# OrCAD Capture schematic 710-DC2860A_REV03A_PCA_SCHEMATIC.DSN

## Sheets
1 PAGE1: size Custom; company: ANALOG DEVICES; note: DEMO BOARD BILL OF MATERIALS; note: 40V,1.2A QUAD STEP-DOWN SILENT SWITCHER uMODULE REGULATOR
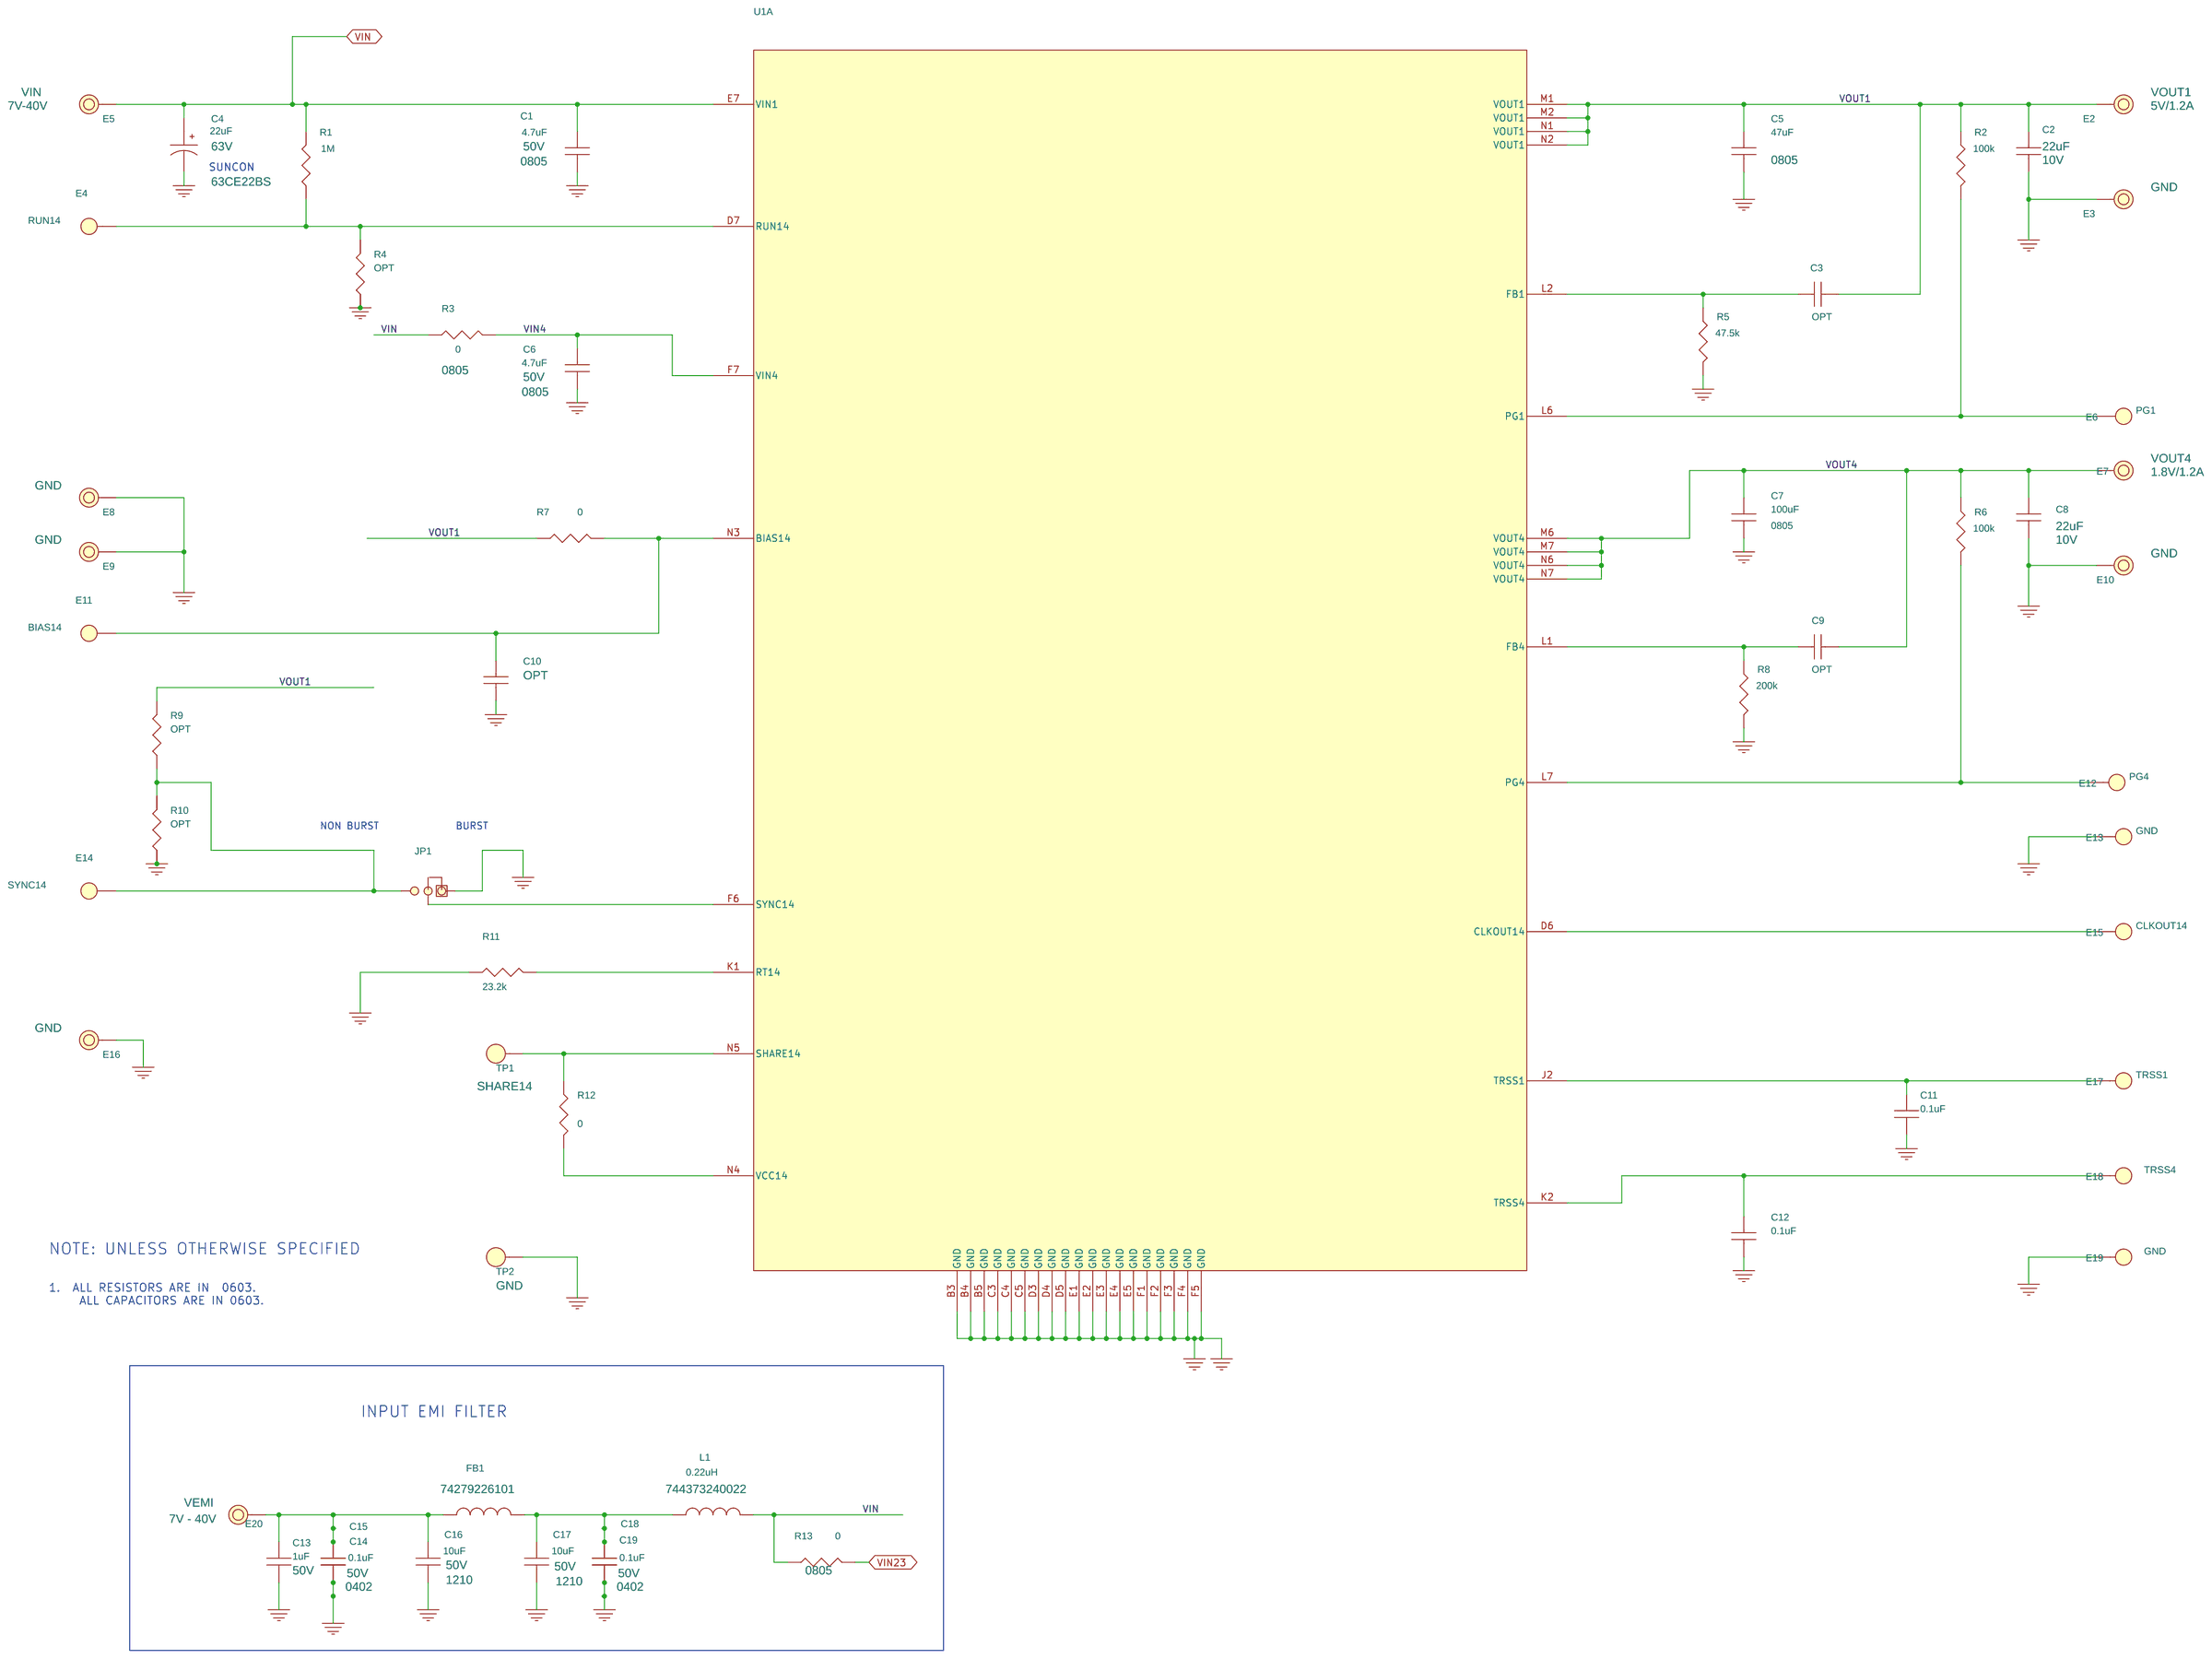
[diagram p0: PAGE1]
2 PAGE2: size Custom
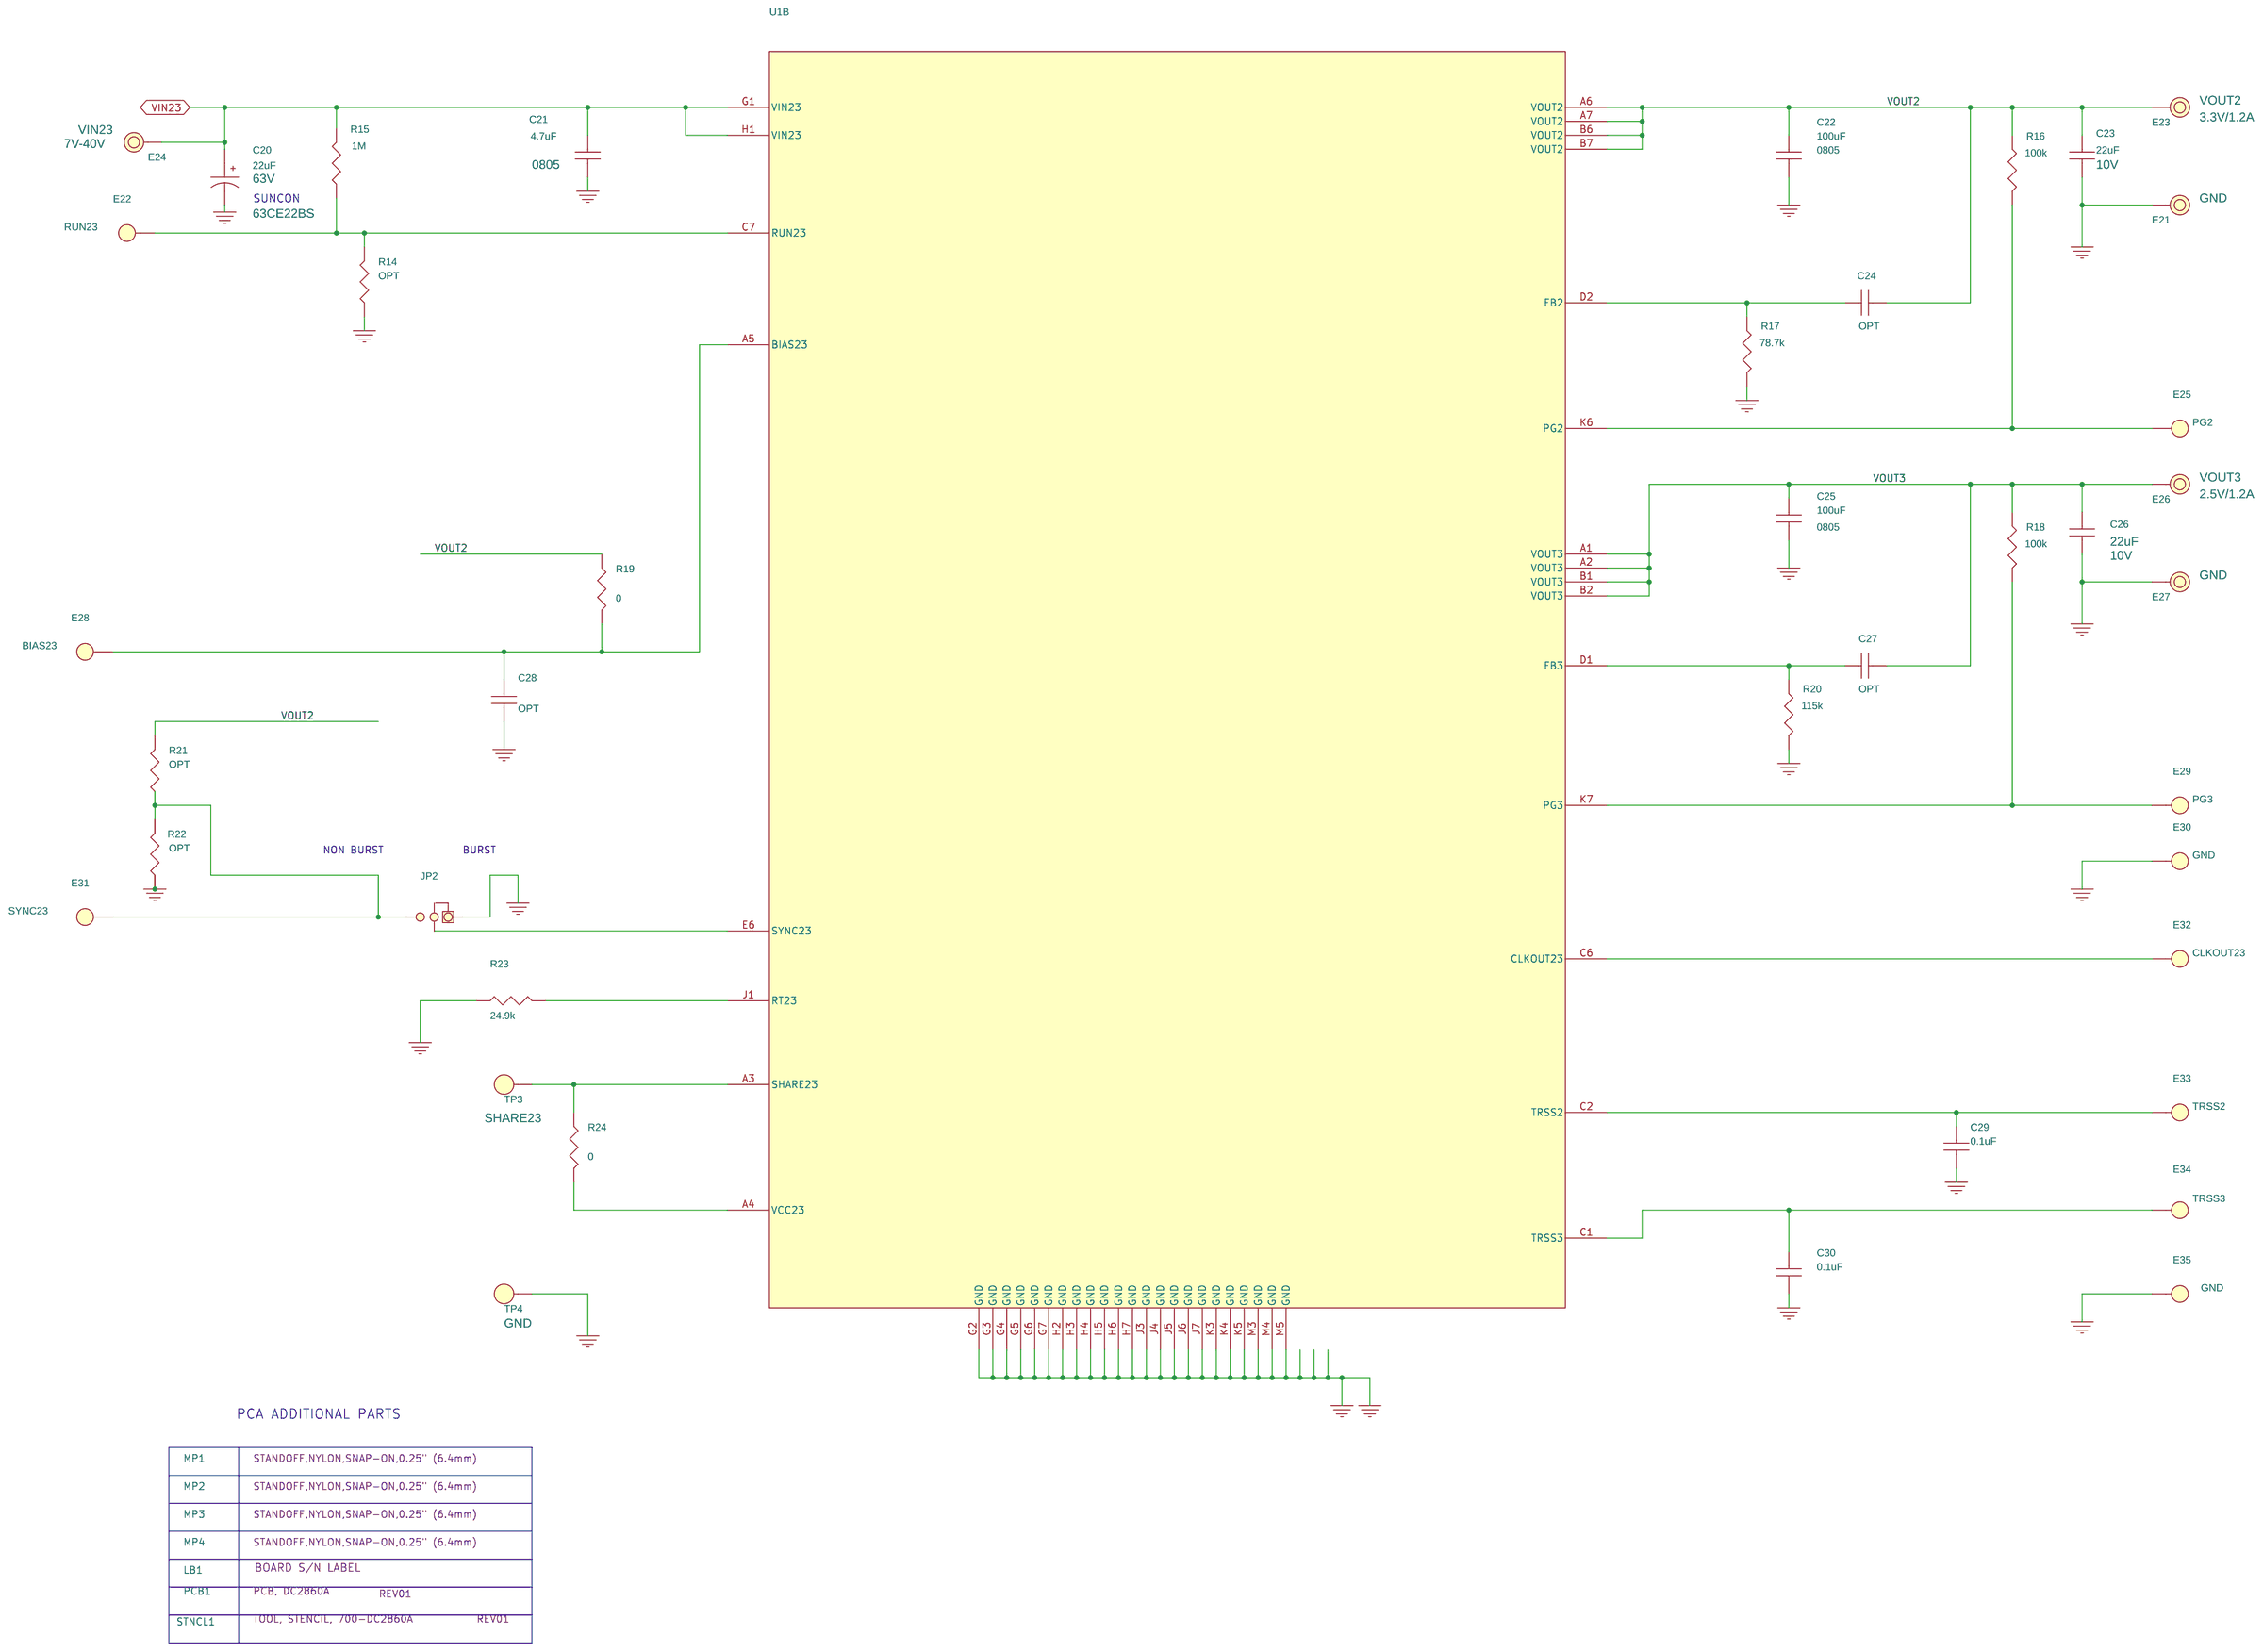
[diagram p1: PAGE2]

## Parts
sheet PAGE1
C1  4.7uF  [CC0805N]
C2  22uF  [CC0603N]
C3  OPT  [CC0603N]
C4  22uF  [SUNCON_CE-BS_6.3X7.7]
C5  47uF  [CC0805N]
C6  4.7uF  [CC0805N]
C7  100uF  [CC0805N]
C8  22uF  [CC0603N]
C9  OPT  [CC0603N]
C10  OPT  [CC0603N]
C11  0.1uF  [CC0603N]
C12  0.1uF  [CC0603N]
C13  1uF  [CC0603N]
C14  0.1uF  [CC0402N]
C15  0.1uF  [CC0402N]
C16  10uF  [CC1210N]
C17  10uF  [CC1210N]
C18  0.1uF  [CC0402N]
C19  0.1uF  [CC0402N]
E2  TEST POINT  [MILLMAX2501]
E3  TEST POINT  [MILLMAX2501]
E4  TEST POINT  [MILLMAX2308]
E5  TEST POINT  [MILLMAX2501]
E6  TEST POINT  [MILLMAX2308]
E7  TEST POINT  [MILLMAX2501]
E8  TEST POINT  [MILLMAX2501]
E9  TEST POINT  [MILLMAX2501]
E10  TEST POINT  [MILLMAX2501]
E11  TEST POINT  [MILLMAX2308]
E12  TEST POINT  [MILLMAX2308]
E13  TEST POINT  [MILLMAX2308]
E14  TEST POINT  [MILLMAX2308]
E15  TEST POINT  [MILLMAX2308]
E16  TEST POINT  [MILLMAX2501]
E17  TEST POINT  [MILLMAX2308]
E18  TEST POINT  [MILLMAX2308]
E19  TEST POINT  [MILLMAX2308]
E20  TEST POINT  [MILLMAX2501]
FB1  100 OHMS@100MHz  [WURTH-74279226101]
JP1  HDR.  [HD1X3-079]
L1  0.22uH  [WURTH-744373240022]
R1  1M  [CR0603N]
R2  100k  [CR0603N]
R3  0  [CR0805N]
R4  OPT  [CR0603N]
R5  47.5k  [CR0603N]
R6  100k  [CR0603N]
R7  0  [CR0603N]
R8  200k  [CR0603N]
R9  OPT  [CR0603N]
R10  OPT  [CR0603N]
R11  23.2k  [CR0603N]
R12  0  [CR0603N]
R13  0  [CR0805N]
TP1  SHARE14  [TEST-PIN]
TP2  GND  [TEST-PIN]
XJP1  SHUNT
sheet PAGE2
C20  22uF  [SUNCON_CE-BS_6.3X7.7]
C21  4.7uF  [CC0805N]
C22  100uF  [CC0805N]
C23  22uF  [CC0603N]
C24  OPT  [CC0603N]
C25  100uF  [CC0805N]
C26  22uF  [CC0603N]
C27  OPT  [CC0603N]
C28  OPT  [CC0603N]
C29  0.1uF  [CC0603N]
C30  0.1uF  [CC0603N]
E21  TEST POINT  [MILLMAX2501]
E22  TEST POINT  [MILLMAX2308]
E23  TEST POINT  [MILLMAX2501]
E24  TEST POINT  [MILLMAX2501]
E25  TEST POINT  [MILLMAX2308]
E26  TEST POINT  [MILLMAX2501]
E27  TEST POINT  [MILLMAX2501]
E28  TEST POINT  [MILLMAX2308]
E29  TEST POINT  [MILLMAX2308]
E30  TEST POINT  [MILLMAX2308]
E31  TEST POINT  [MILLMAX2308]
E32  TEST POINT  [MILLMAX2308]
E33  TEST POINT  [MILLMAX2308]
E34  TEST POINT  [MILLMAX2308]
E35  TEST POINT  [MILLMAX2308]
JP2  HDR.  [HD1X3-079]
LB1  LABEL  [895-0154_REV01]
MP1  STANDOFF  [MTG-8831]
MP2  STANDOFF  [MTG-8831]
MP3  STANDOFF  [MTG-8831]
MP4  STANDOFF  [MTG-8831]
PCB1  PCB, DC2860A
R14  OPT  [CR0603N]
R15  1M  [CR0603N]
R16  100k  [CR0603N]
R17  78.7k  [CR0603N]
R18  100k  [CR0603N]
R19  0  [CR0603N]
R20  115k  [CR0603N]
R21  OPT  [CR0603N]
R22  OPT  [CR0603N]
R23  24.9k  [CR0603N]
R24  0  [CR0603N]
STNCL1  TOOL, STENCIL, 700-DC2860A
TP3  SHARE23  [TEST-PIN]
TP4  GND  [TEST-PIN]
U1  LTM8051-BGA  [LTC-BGA-91-1608]  (sections A,B)
XJP2  SHUNT

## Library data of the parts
C1 C6 = CAP: CAP.,4.7uF,X5R,50V,10%,0805; CLASS: DISCRETE; Dielectric Type: X5R; FPLIST: CC0805N,CC0805L,CC0805M; Inventory Qty: 8500; Manufacturer: MURATA; Manufacturer PN: GRM21BR61H475KE51L; PART_NUMBER: 150-0172; Package Size: 0805; Rated Voltage: 50V; Tolerance: 10%
C2 C8 = CAP: CAP.,22uF,X5R,10V,20%,0603; CLASS: DISCRETE; Dielectric Type: X5R; FPLIST: CC0603N,CC0603L,CC0603M; Inventory Qty: 17834; Manufacturer: AVX; Manufacturer PN: 0603ZD226MAT2A; PART_NUMBER: 150-2341; Package Size: 0603; Package Type: Surface Mount, MLCC; Rated Voltage: 10V; Temperature Coefficient: X5R; Tolerance: 20%
C3 C9 C10 = CAP: CAP., OPTION, 0603; CLASS: DISCRETE; FPLIST: CC0603N,CC0603L,CC0603M; PART_NUMBER: 150-3038; Package Size: 0603; Package Type: SMD
C4 C20 = CAP_P_ALT: CAP.,22uF,ALUM. ELECT.,63V,20%,6.3x7.7mm,CE-BS; CLASS: DISCRETE; Dielectric Type: ALUM. ELECT.; Inventory Qty: 8902; Manufacturer: SUN ELECTRONIC INDUSTRIES CORP; Manufacturer PN: 63CE22BS; PART_NUMBER: 150-3334; Package Size: 6.3x7.7mm; Rated Voltage: 63V; Tolerance: 20%
C5 = CAP: CAP.,47uF,X5R,6.3V,20%,0805; CLASS: DISCRETE; Dielectric Type: X5R; FPLIST: CC0805N,CC0805L,CC0805M; Inventory Qty: 29976; Manufacturer: MURATA; Manufacturer PN: GRM21BR60J476ME15L; PART_NUMBER: 150-0140; Package Size: 0805; Rated Voltage: 6.3V; Tolerance: 20%
C7 = CAP: CAP.,100uF,X5R,6.3V,20%,0805; CLASS: DISCRETE; Dielectric Type: X5R; FPLIST: CC0805N,CC0805L,CC0805M; Inventory Qty: 2920; Manufacturer: MURATA; Manufacturer PN: GRM21BR60J107ME15K; PART_NUMBER: 150-0728; Package Size: 0805; Package Type: Surface Mount, MLCC; Rated Voltage: 6.3V; Temperature Coefficient: X5R; Tolerance: 20%
C11 C12 = CAP: CAP.,0.1uF,X5R,16V,10%,0603; CLASS: DISCRETE; Dielectric Type: X5R; FPLIST: CC0603N,CC0603L,CC0603M; Inventory Qty: 21908; Manufacturer: AVX; Manufacturer PN: 0603YD104KAT2A; PART_NUMBER: 150-3328; Package Size: 0603; Rated Voltage: 16V; Tolerance: 10%
C13 = CAP: CAP.,1uF,X5R,50V,10%,0603; CLASS: DISCRETE; Dielectric Type: X5R; FPLIST: CC0603N,CC0603L,CC0603M; Inventory Qty: 11686; Manufacturer: AVX; Manufacturer PN: 06035D105KAT2A; PART_NUMBER: 150-3292; Package Size: 0603; Package Type: SMD; Rated Voltage: 50V; Tolerance: 10%
C14 C15 C18 C19 = CAP: CAP.,0.1uF,X7R,50V,10%,0402; CLASS: DISCRETE; Dielectric Type: X7R; FPLIST: CC0402N,CC0402L,CC0402M; Inventory Qty: 320056; Manufacturer: AVX; Manufacturer PN: 04025C104KAT2A; PART_NUMBER: 150-3240; Package Size: 0402; Package Type: SMD; Rated Voltage: 50V; Tolerance: 10%
C16 C17 = CAP: CAP.,10uF,X5R,50V,10%,1210; CLASS: DISCRETE; Dielectric Type: X5R; FPLIST: CC1210N,CC1210L,CC1210M; Inventory Qty: 11106; Manufacturer: TDK; Manufacturer PN: C3225X5R1H106K250AB; PART_NUMBER: 150-3288; Package Size: 1210; Rated Voltage: 50V; Tolerance: 10%
E2 = TESTPOINT_.219_MILL-MAX_2501: TEST POINT,TURRET,0.094" MTG. HOLE,PCB 0.062" THK; CLASS: IO; Inventory Qty: 444100; Manufacturer: MILL-MAX; Manufacturer PN: 2501-2-00-80-00-00-07-0; PART_FIELD_01: VOUT1; PART_FIELD_02: 5V/1.2A; PART_NUMBER: 260-0003
E3 E8 E21 E27 = TESTPOINT_.219_MILL-MAX_2501: TEST POINT,TURRET,0.094" MTG. HOLE,PCB 0.062" THK; CLASS: IO; Inventory Qty: 444100; Manufacturer: MILL-MAX; Manufacturer PN: 2501-2-00-80-00-00-07-0; PART_FIELD_01: GND; PART_NUMBER: 260-0003
E4 = TEST_POINT_.156_MILL-MAX_2308: TEST POINT,TURRET,0.064" MTG. HOLE,PCB 0.062" THK; CLASS: IO; Inventory Qty: 751543; Manufacturer: MILL-MAX; Manufacturer PN: 2308-2-00-80-00-00-07-0; PART_FIELD_01: RUN14; PART_NUMBER: 260-0004
E5 = TESTPOINT_.219_MILL-MAX_2501: TEST POINT,TURRET,0.094" MTG. HOLE,PCB 0.062" THK; CLASS: IO; Inventory Qty: 444100; Manufacturer: MILL-MAX; Manufacturer PN: 2501-2-00-80-00-00-07-0; PART_FIELD_01: VIN; PART_FIELD_02: 7V-40V; PART_NUMBER: 260-0003
E6 = TEST_POINT_.156_MILL-MAX_2308: TEST POINT,TURRET,0.064" MTG. HOLE,PCB 0.062" THK; CLASS: IO; Inventory Qty: 751543; Manufacturer: MILL-MAX; Manufacturer PN: 2308-2-00-80-00-00-07-0; PART_FIELD_01: PG1; PART_NUMBER: 260-0004
E7 = TESTPOINT_.219_MILL-MAX_2501: TEST POINT,TURRET,0.094" MTG. HOLE,PCB 0.062" THK; CLASS: IO; Inventory Qty: 444100; Manufacturer: MILL-MAX; Manufacturer PN: 2501-2-00-80-00-00-07-0; PART_FIELD_01: VOUT4; PART_FIELD_02: 1.8V/1.2A; PART_NUMBER: 260-0003
E9 E10 E16 = TESTPOINT_.219_MILL-MAX_2501: TEST POINT,TURRET,0.094" MTG. HOLE,PCB 0.062" THK; CLASS: IO; Inventory Qty: 444100; Manufacturer: MILL-MAX; Manufacturer PN: 2501-2-00-80-00-00-07-0; PART_FIELD_01: GND; PART_FIELD_02: <PART_FIELD_02>; PART_NUMBER: 260-0003
E11 = TEST_POINT_.156_MILL-MAX_2308: TEST POINT,TURRET,0.064" MTG. HOLE,PCB 0.062" THK; CLASS: IO; Inventory Qty: 751543; Manufacturer: MILL-MAX; Manufacturer PN: 2308-2-00-80-00-00-07-0; PART_FIELD_01: BIAS14; PART_NUMBER: 260-0004
E12 = TEST_POINT_.156_MILL-MAX_2308: TEST POINT,TURRET,0.064" MTG. HOLE,PCB 0.062" THK; CLASS: IO; Inventory Qty: 751543; Manufacturer: MILL-MAX; Manufacturer PN: 2308-2-00-80-00-00-07-0; PART_FIELD_01: PG4; PART_NUMBER: 260-0004
E13 E19 E30 E35 = TEST_POINT_.156_MILL-MAX_2308: TEST POINT,TURRET,0.064" MTG. HOLE,PCB 0.062" THK; CLASS: IO; Inventory Qty: 751543; Manufacturer: MILL-MAX; Manufacturer PN: 2308-2-00-80-00-00-07-0; PART_FIELD_01: GND; PART_NUMBER: 260-0004
E14 = TEST_POINT_.156_MILL-MAX_2308: TEST POINT,TURRET,0.064" MTG. HOLE,PCB 0.062" THK; CLASS: IO; Inventory Qty: 751543; Manufacturer: MILL-MAX; Manufacturer PN: 2308-2-00-80-00-00-07-0; PART_FIELD_01: SYNC14; PART_NUMBER: 260-0004
E15 = TEST_POINT_.156_MILL-MAX_2308: TEST POINT,TURRET,0.064" MTG. HOLE,PCB 0.062" THK; CLASS: IO; Inventory Qty: 751543; Manufacturer: MILL-MAX; Manufacturer PN: 2308-2-00-80-00-00-07-0; PART_FIELD_01: CLKOUT14; PART_NUMBER: 260-0004
E17 = TEST_POINT_.156_MILL-MAX_2308: TEST POINT,TURRET,0.064" MTG. HOLE,PCB 0.062" THK; CLASS: IO; Inventory Qty: 751543; Manufacturer: MILL-MAX; Manufacturer PN: 2308-2-00-80-00-00-07-0; PART_FIELD_01: TRSS1; PART_NUMBER: 260-0004
E18 = TEST_POINT_.156_MILL-MAX_2308: TEST POINT,TURRET,0.064" MTG. HOLE,PCB 0.062" THK; CLASS: IO; Inventory Qty: 751543; Manufacturer: MILL-MAX; Manufacturer PN: 2308-2-00-80-00-00-07-0; PART_FIELD_01: TRSS4; PART_NUMBER: 260-0004
E20 = TESTPOINT_.219_MILL-MAX_2501: TEST POINT,TURRET,0.094" MTG. HOLE,PCB 0.062" THK; CLASS: IO; Inventory Qty: 444100; Manufacturer: MILL-MAX; Manufacturer PN: 2501-2-00-80-00-00-07-0; PART_FIELD_01: VEMI; PART_FIELD_02: 7V - 40V; PART_NUMBER: 260-0003
FB1 = IND_ALT: IND.,100 OHMS@100MHz,FERRITE BEAD,25%,8A,6mOHMS,1812; CLASS: DISCRETE; Inventory Qty: 2470; Manufacturer: WURTH ELEKTRONIK; Manufacturer PN: 74279226101; PART_NUMBER: 200-0280; Package Size: 1812; Tolerance: 25%
JP1 JP2 = 1X3_H: CONN.,HDR.,MALE,1x3,2mm,THT, STR,NO SUBS. ALLOWED; CLASS: IO; Inventory Qty: 9584; Manufacturer: SAMTEC; Manufacturer PN: TMM-103-02-L-S; PART_NUMBER: 250-0638
L1 = IND_ALT: IND.,0.22uH,PWR,SHIELDED,30%,9.5A,7.3mOHMS,4020; CLASS: DISCRETE; Inventory Qty: 0; Manufacturer: WURTH ELEKTRONIK; Manufacturer PN: 744373240022; PART_NUMBER: 200-0481; Package Size: 4020; Tolerance: 30%
R1 = RES: RES.,1M OHM,1%,1/10W,0603,AEC-Q200; CLASS: DISCRETE; FPLIST: CR0603N,CR0603L,CR0603M; Inventory Qty: 139597; Manufacturer: VISHAY; Manufacturer PN: CRCW06031M00FKEA; PART_NUMBER: 100-0335; Package Size: 0603; Rated Power: 1/10W; Temperature Coefficient: 100ppm; Tolerance: 1%
R2 R6 = RES: RES.,100k OHMS,1%,1/10W,0603,AEC-Q200; CLASS: DISCRETE; FPLIST: CR0603N,CR0603L,CR0603M; Inventory Qty: 185496; Manufacturer: VISHAY; Manufacturer PN: CRCW0603100KFKEA; PART_NUMBER: 100-0343; Package Size: 0603; Rated Power: 1/10W; Temperature Coefficient: +/-100ppm; Tolerance: 1%
R3 R13 = RES: RES.,0 OHM,1/8W,0805; CLASS: DISCRETE; FPLIST: CR0805N,CR0805L,CR0805M; Inventory Qty: 89206; Manufacturer: VISHAY; Manufacturer PN: CRCW08050000Z0EA; PART_NUMBER: 100-0024; Package Size: 0805; Rated Power: 1/8W
R4 R9 R10 = RES: RES., OPTION, 0603; CLASS: DISCRETE; FPLIST: CR0603N,CR0603L,CR0603M; PART_NUMBER: 100-2374; Package Size: 0603
R5 = RES: RES.,47.5k OHMS,1%,1/10W,0603; CLASS: DISCRETE; FPLIST: CR0603N,CR0603L,CR0603M; Inventory Qty: 58285; Manufacturer: VISHAY; Manufacturer PN: CRCW060347K5FKEA; PART_NUMBER: 100-2554; Package Size: 0603; Rated Power: 1/10W; Temperature Coefficient: 100ppm/C; Tolerance: 1%
R7 R12 = RES: RES.,0 OHM,1/10W,0603,AEC-Q200; CLASS: DISCRETE; FPLIST: CR0603N,CR0603L,CR0603M; Inventory Qty: 589551; Manufacturer: VISHAY; Manufacturer PN: CRCW06030000Z0EA; PART_NUMBER: 100-0009; Package Size: 0603; Rated Power: 1/10W
R8 = RES: RES.,200k OHMS,1%,1/10W,0603; CLASS: DISCRETE; FPLIST: CR0603N,CR0603L,CR0603M; Inventory Qty: 116426; Manufacturer: NIC; Manufacturer PN: NRC06F2003TRF; PART_NUMBER: 100-2378; Package Size: 0603; Rated Power: 1/10W; Temperature Coefficient: 100ppm/C; Tolerance: 1%
R11 = RES: RES.,23.2k OHMS,1%,1/10W,0603; CLASS: DISCRETE; FPLIST: CR0603N,CR0603L,CR0603M; Inventory Qty: 14790; Manufacturer: KOA SPEER; Manufacturer PN: RK73H1JTTD2322F; PART_NUMBER: 100-0355; Package Size: 0603; Rated Power: 1/10W; Temperature Coefficient: 100ppm/C; Tolerance: 1%
TP1 TP2 = TURRET-2501_1
XJP1 XJP2 = SHNT_A: CONN.,SHUNT,FEMALE,2-POS,2mm; CLASS: IO; Inventory Qty: 92366; Manufacturer: SAMTEC; Manufacturer PN: 2SN-BK-G; PART_NUMBER: 250-0419
C21 = CAP: CAP.,4.7uF,X5R,50V,10%,0805; CLASS: DISCRETE; Dielectric Type: X5R; Discriptions: CAP.,X5R, 4.7uF,50V,20% 1210; FPLIST: CC0805N,CC0805L,CC0805M; Inventory Qty: 8500; Manufacturer: MURATA; Manufacturer PN: GRM21BR61H475KE51L; PART_NUMBER: 150-0172; Package Size: 0805; Rated Voltage: 50V; Tolerance: 10%
C22 C25 = CAP: CAP.,100uF,X5R,6.3V,20%,0805; CLASS: DISCRETE; Dielectric Type: X5R; Discriptions: CAP.,X5R,100uF, 10V,20%,1210; FPLIST: CC0805N,CC0805L,CC0805M; Inventory Qty: 2920; Manufacturer: MURATA; Manufacturer PN: GRM21BR60J107ME15K; PART_NUMBER: 150-0728; Package Size: 0805; Package Type: Surface Mount, MLCC; Rated Voltage: 6.3V; Temperature Coefficient: X5R; Tolerance: 20%
C23 C26 = CAP: CAP.,22uF,X5R,10V,20%,0603; CLASS: DISCRETE; Dielectric Type: X5R; Discriptions: CAP. , OPT, 0603; FPLIST: CC0603N,CC0603L,CC0603M; Inventory Qty: 17834; Manufacturer: AVX; Manufacturer PN: 0603ZD226MAT2A; PART_NUMBER: 150-2341; Package Size: 0603; Package Type: Surface Mount, MLCC; Rated Voltage: 10V; Temperature Coefficient: X5R; Tolerance: 20%
C24 C27 C28 = CAP: CAP., OPTION, 0603; CLASS: DISCRETE; Discriptions: CAP. , OPT, 0603; FPLIST: CC0603N,CC0603L,CC0603M; PART_NUMBER: 150-3038; Package Size: 0603; Package Type: SMD
C29 C30 = CAP: CAP.,0.1uF,X5R,16V,10%,0603; CLASS: DISCRETE; Dielectric Type: X5R; Discriptions: CAP., X5R,0.1uF,16V,20%,0603; FPLIST: CC0603N,CC0603L,CC0603M; Inventory Qty: 21908; Manufacturer: AVX; Manufacturer PN: 0603YD104KAT2A; PART_NUMBER: 150-3328; Package Size: 0603; Rated Voltage: 16V; Tolerance: 10%
E22 = TEST_POINT_.156_MILL-MAX_2308: TEST POINT,TURRET,0.064" MTG. HOLE,PCB 0.062" THK; CLASS: IO; Inventory Qty: 751543; Manufacturer: MILL-MAX; Manufacturer PN: 2308-2-00-80-00-00-07-0; PART_FIELD_01: RUN23; PART_NUMBER: 260-0004
E23 = TESTPOINT_.219_MILL-MAX_2501: TEST POINT,TURRET,0.094" MTG. HOLE,PCB 0.062" THK; CLASS: IO; Inventory Qty: 444100; Manufacturer: MILL-MAX; Manufacturer PN: 2501-2-00-80-00-00-07-0; PART_FIELD_01: VOUT2; PART_FIELD_02: 3.3V/1.2A; PART_NUMBER: 260-0003
E24 = TESTPOINT_.219_MILL-MAX_2501: TEST POINT,TURRET,0.094" MTG. HOLE,PCB 0.062" THK; CLASS: IO; Inventory Qty: 444100; Manufacturer: MILL-MAX; Manufacturer PN: 2501-2-00-80-00-00-07-0; PART_FIELD_01: VIN23; PART_FIELD_02: 7V-40V; PART_NUMBER: 260-0003
E25 = TEST_POINT_.156_MILL-MAX_2308: TEST POINT,TURRET,0.064" MTG. HOLE,PCB 0.062" THK; CLASS: IO; Inventory Qty: 751543; Manufacturer: MILL-MAX; Manufacturer PN: 2308-2-00-80-00-00-07-0; PART_FIELD_01: PG2; PART_NUMBER: 260-0004
E26 = TESTPOINT_.219_MILL-MAX_2501: TEST POINT,TURRET,0.094" MTG. HOLE,PCB 0.062" THK; CLASS: IO; Inventory Qty: 444100; Manufacturer: MILL-MAX; Manufacturer PN: 2501-2-00-80-00-00-07-0; PART_FIELD_01: VOUT3; PART_FIELD_02: 2.5V/1.2A; PART_NUMBER: 260-0003
E28 = TEST_POINT_.156_MILL-MAX_2308: TEST POINT,TURRET,0.064" MTG. HOLE,PCB 0.062" THK; CLASS: IO; Inventory Qty: 751543; Manufacturer: MILL-MAX; Manufacturer PN: 2308-2-00-80-00-00-07-0; PART_FIELD_01: BIAS23; PART_NUMBER: 260-0004
E29 = TEST_POINT_.156_MILL-MAX_2308: TEST POINT,TURRET,0.064" MTG. HOLE,PCB 0.062" THK; CLASS: IO; Inventory Qty: 751543; Manufacturer: MILL-MAX; Manufacturer PN: 2308-2-00-80-00-00-07-0; PART_FIELD_01: PG3; PART_NUMBER: 260-0004
E31 = TEST_POINT_.156_MILL-MAX_2308: TEST POINT,TURRET,0.064" MTG. HOLE,PCB 0.062" THK; CLASS: IO; Inventory Qty: 751543; Manufacturer: MILL-MAX; Manufacturer PN: 2308-2-00-80-00-00-07-0; PART_FIELD_01: SYNC23; PART_NUMBER: 260-0004
E32 = TEST_POINT_.156_MILL-MAX_2308: TEST POINT,TURRET,0.064" MTG. HOLE,PCB 0.062" THK; CLASS: IO; Inventory Qty: 751543; Manufacturer: MILL-MAX; Manufacturer PN: 2308-2-00-80-00-00-07-0; PART_FIELD_01: CLKOUT23; PART_NUMBER: 260-0004
E33 = TEST_POINT_.156_MILL-MAX_2308: TEST POINT,TURRET,0.064" MTG. HOLE,PCB 0.062" THK; CLASS: IO; Inventory Qty: 751543; Manufacturer: MILL-MAX; Manufacturer PN: 2308-2-00-80-00-00-07-0; PART_FIELD_01: TRSS2; PART_NUMBER: 260-0004
E34 = TEST_POINT_.156_MILL-MAX_2308: TEST POINT,TURRET,0.064" MTG. HOLE,PCB 0.062" THK; CLASS: IO; Inventory Qty: 751543; Manufacturer: MILL-MAX; Manufacturer PN: 2308-2-00-80-00-00-07-0; PART_FIELD_01: TRSS3; PART_NUMBER: 260-0004
LB1 = BLANK_LABEL: LABEL SPEC, DEMO BOARD SERIAL NUMBER; Inventory Qty: 0; Manufacturer: BRADY; Manufacturer PN: THT-96-717-10; PART_FIELD_01: BOARD S/N LABEL; PART_NUMBER: 895-0154
MP1-MP4 = BLANK_MECHANICAL_PART: STANDOFF,NYLON,SNAP-ON,0.25" (6.4mm); CLASS: DISCRETE; Inventory Qty: 188664; Manufacturer: KEYSTONE; Manufacturer PN: 8831; PART_NUMBER: 763-0006
PCB1 = BLANK_PCB_PART: BOM Notes: REV01; CLASS: DISCRETE; Inventory Qty: 0; Manufacturer: PHASE 3; Manufacturer PN: 600-DC2860A; PART_NUMBER: 600-DC2860A
R14 R21 R22 = RES: RES., OPTION, 0603; CLASS: DISCRETE; Discriptions: RES., OPT, 0603; FPLIST: CR0603N,CR0603L,CR0603M; PART_NUMBER: 100-2374; Package Size: 0603
R15 = RES: RES.,1M OHM,1%,1/10W,0603,AEC-Q200; CLASS: DISCRETE; Discriptions: RES., 1M, 0603; FPLIST: CR0603N,CR0603L,CR0603M; Inventory Qty: 139597; Manufacturer: VISHAY; Manufacturer PN: CRCW06031M00FKEA; PART_NUMBER: 100-0335; Package Size: 0603; Rated Power: 1/10W; Temperature Coefficient: 100ppm; Tolerance: 1%
R16 = RES: RES.,100k OHMS,1%,1/10W,0603,AEC-Q200; CLASS: DISCRETE; Discriptions: RES., 100K,0.06W, 5%,06032; FPLIST: CR0603N,CR0603L,CR0603M; Inventory Qty: 185496; Manufacturer: VISHAY; Manufacturer PN: CRCW0603100KFKEA; PART_NUMBER: 100-0343; Package Size: 0603; Rated Power: 1/10W; Temperature Coefficient: +/-100ppm; Tolerance: 1%
R17 = RES: RES.,78.7k OHMS,1%,1/10W,0603; CLASS: DISCRETE; Discriptions: RES., 47.5K,W, %,0603; FPLIST: CR0603N,CR0603L,CR0603M; Inventory Qty: 35000; Manufacturer: NIC; Manufacturer PN: NRC06F7872TRF; PART_NUMBER: 100-0291; Package Size: 0603; Rated Power: 1/10W; Temperature Coefficient: 100ppm/C; Tolerance: 1%
R18 = RES: RES.,100k OHMS,1%,1/10W,0603,AEC-Q200; CLASS: DISCRETE; Discriptions: RES., 100K,0.06W, 5%,0603; FPLIST: CR0603N,CR0603L,CR0603M; Inventory Qty: 185496; Manufacturer: VISHAY; Manufacturer PN: CRCW0603100KFKEA; PART_NUMBER: 100-0343; Package Size: 0603; Rated Power: 1/10W; Temperature Coefficient: +/-100ppm; Tolerance: 1%
R19 R24 = RES: RES.,0 OHM,1/10W,0603,AEC-Q200; CLASS: DISCRETE; Discriptions: RES., OPT, 0603; FPLIST: CR0603N,CR0603L,CR0603M; Inventory Qty: 589551; Manufacturer: VISHAY; Manufacturer PN: CRCW06030000Z0EA; PART_NUMBER: 100-0009; Package Size: 0603; Rated Power: 1/10W
R20 = RES: RES.,115k OHMS,1%,1/10W,0603; CLASS: DISCRETE; Discriptions: RES., 78.7K,W, %,0603; FPLIST: CR0603N,CR0603L,CR0603M; Inventory Qty: 23218; Manufacturer: NIC; Manufacturer PN: NRC06F1153TRF; PART_NUMBER: 100-2580; Package Size: 0603; Rated Power: 1/10W; Temperature Coefficient: 100ppm; Tolerance: 1%
R23 = RES: RES.,24.9k OHMS,1%,1/10W,0603,AEC-Q200; CLASS: DISCRETE; Discriptions: RES., 41.2K,0.06W, 5%,0603; FPLIST: CR0603N,CR0603L,CR0603M; Inventory Qty: 12542; Manufacturer: NIC; Manufacturer PN: NRC06F2492TRF; PART_NUMBER: 100-0037; Package Size: 0603; Rated Power: 1/10W; Temperature Coefficient: 100ppm/C; Tolerance: 1%
STNCL1 = BLANK_STENCIL_PART: BOM Notes: REV01; CLASS: DISCRETE; Inventory Qty: 0; Manufacturer: ANALOG DEVICES; Manufacturer PN: 830--DC2860A; PART_NUMBER: 830-DC2860A
TP3 TP4 = TURRET-2501_1: Discriptions: TEST POINT
U1 = LTM8051-BGA: IC,40V,2A Quad Step-Down uModule Regulator,BGA; CLASS: IC; Inventory Qty: 0; Manufacturer: ANALOG DEVICES; Manufacturer PN: LTM8051EY#PBF; PART_NUMBER: LTM8051EY#PBF; Package Type: uModule Regulator,BGA

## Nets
GND: C1.2 C2.2 C4.2 C5.2 C6.2 C7.2 C8.2 C10.2 C11.2 C12.2 C13.2 C14.2 C15.2 C16.2 C17.2 C18.2 C19.2 C20.2 C21.2 C22.2 C23.2 C25.2 C26.2 C28.2 C29.2 C30.2 E3.1 E8.1 E9.1 E10.1 E13.1(A) E16.1 E19.1(A) E21.1 E27.1 E30.1(A) E35.1(A) JP1.1 JP2.1 R4.1 R5.2 R8.2 R10.1 R11.1 R14.1 R17.2 R20.2 R22.1 R23.1 TP2.1 TP4.1 U1.B3(GND) U1.B4(GND) U1.B5(GND) U1.C3(GND) U1.C4(GND) U1.C5(GND) U1.D3(GND) U1.D4(GND) U1.D5(GND) U1.E1(GND) U1.E2(GND) U1.E3(GND) U1.E4(GND) U1.E5(GND) U1.F1(GND) U1.F2(GND) U1.F3(GND) U1.F4(GND) U1.F5(GND) U1.G2(GND) U1.G3(GND) U1.G4(GND) U1.G5(GND) U1.G6(GND) U1.G7(GND) U1.H2(GND) U1.H3(GND) U1.H4(GND) U1.H5(GND) U1.H6(GND) U1.H7(GND) U1.J3(GND) U1.J4(GND) U1.J5(GND) U1.J6(GND) U1.J7(GND) U1.K3(GND) U1.K4(GND) U1.K5(GND) U1.M3(GND) U1.M4(GND) U1.M5(GND)
VIN: C1.1 C4.1 E5.1 L1.2 R1.2 R3.1 R13.1 U1.E7(VIN1)
VIN4: C6.1 R3.2 U1.F7(VIN4)
VIN23: C20.1 C21.1 E24.1 R13.2 R15.2 U1.G1(VIN23) U1.H1(VIN23)
VOUT1: C2.1 C3.2 C5.1 E2.1 R2.1 R7.1 R9.2 U1.M1(VOUT1) U1.M2(VOUT1) U1.N1(VOUT1) U1.N2(VOUT1)
VOUT2: C22.1 C23.1 C24.2 E23.1 R16.1 R19.1 R21.2 U1.A6(VOUT2) U1.A7(VOUT2) U1.B6(VOUT2) U1.B7(VOUT2)
VOUT3: C25.1 C26.1 C27.2 E26.1 R18.1 U1.A1(VOUT3) U1.A2(VOUT3) U1.B1(VOUT3) U1.B2(VOUT3)
VOUT4: C7.1 C8.1 C9.2 E7.1 R6.1 U1.M6(VOUT4) U1.M7(VOUT4) U1.N6(VOUT4) U1.N7(VOUT4)
N18912728: C12.1 E18.1(A) U1.K2(TRSS4)
N18913016: C11.1 E17.1(A) U1.J2(TRSS1)
N18923501: E15.1(A) U1.D6(CLKOUT14)
N18925633: C9.1 R8.1 U1.L1(FB4)
N18925947: C3.1 R5.1 U1.L2(FB1)
N18955521: E12.1(A) R6.2 U1.L7(PG4)
N19072608: E4.1(A) R1.1 R4.2 U1.D7(RUN14)
N19132140: R12.1 TP1.1 U1.N5(SHARE14)
N19175141: E6.1(A) R2.2 U1.L6(PG1)
N19183295: E14.1(A) JP1.3 R9.1 R10.2
N19212391: C10.1 E11.1(A) R7.2 U1.N3(BIAS14)
N19217659: C13.1 C14.1 C15.1 C16.1 E20.1 FB1.1
N19217676: C17.1 C18.1 C19.1 FB1.2 L1.1
N19300560: E25.1(A) R16.2 U1.K6(PG2)
N19300571: E22.1(A) R14.2 R15.1 U1.C7(RUN23)
N19300603: C24.1 R17.1 U1.D2(FB2)
N19300725: E29.1(A) R18.2 U1.K7(PG3)
N19300733: C28.1 E28.1(A) R19.2 U1.A5(BIAS23)
N19300762: C27.1 R20.1 U1.D1(FB3)
N19300808: E31.1(A) JP2.3 R21.1 R22.2
N19300877: JP2.2 U1.E6(SYNC23)
N19300884: E32.1(A) U1.C6(CLKOUT23)
N19300900: R23.2 U1.J1(RT23)
N19300910: R24.1 TP3.1 U1.A3(SHARE23)
N19300924: C29.1 E33.1(A) U1.C2(TRSS2)
N19300950: R24.2 U1.A4(VCC23)
N19300964: C30.1 E34.1(A) U1.C1(TRSS3)
N19348438: JP1.2 U1.F6(SYNC14)
N19348445: R11.2 U1.K1(RT14)
N19348463: R12.2 U1.N4(VCC14)

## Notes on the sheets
sheet 1
- SUNCON
- NON BURST
- BURST
- NOTE: UNLESS OTHERWISE SPECIFIED
- 1.  ALL RESISTORS ARE IN  0603.
       ALL CAPACITORS ARE IN 0603.
- INPUT EMI FILTER
sheet 2
- SUNCON
- NON BURST
- BURST
- PCA ADDITIONAL PARTS
